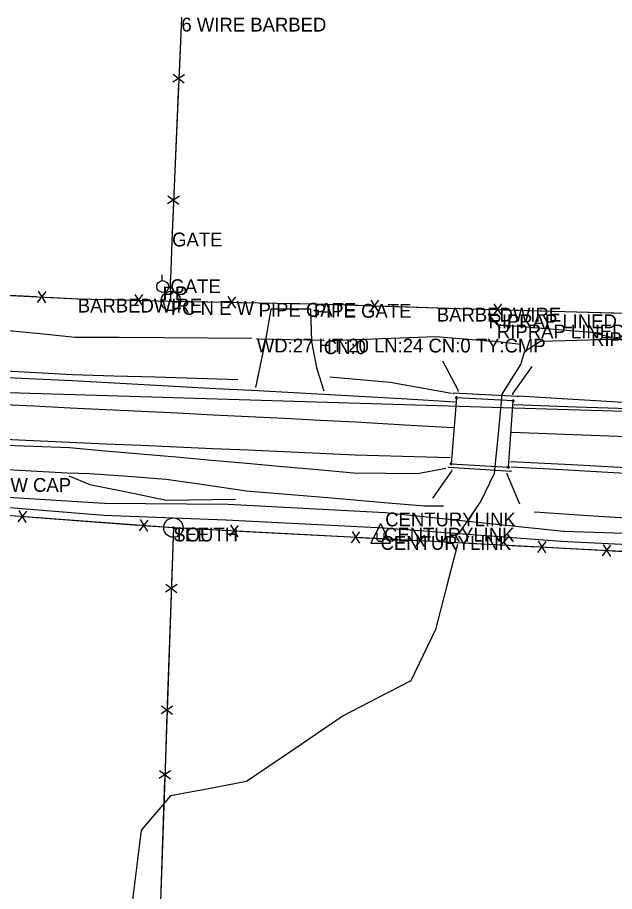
# Model space of a CAD drawing. Extents: x 675481 to 678499, y 212715 to 215285.
# Drawn here: x 676497.8 to 676713.6, y 214534.9 to 214851 of the extents above; entities that cross this region are included whole.
import ezdxf

# ---------------------------------------------------------------- set-up
doc = ezdxf.new("R2010")
doc.units = 0
for name, color, linetype in [('S_BASELINE', 7, 'Continuous'), ('S_BRIDGE', 7, 'Continuous'), ('S_DITCHLINE', 7, 'Continuous'), ('S_DRG_PT_SYM', 7, 'Continuous'), ('S_DRIVEWAY', 7, 'Continuous'), ('S_EDGE_PAVEMENT', 7, 'Continuous'), ('S_FENCE', 7, 'Continuous'), ('S_FENCE_ANNOT', 7, 'Continuous'), ('S_FIBER_OPTIC_CABLE', 7, 'Continuous'), ('S_FIBER_OPTIC_CABLE_ANNOT', 7, 'Continuous'), ('S_GATE', 7, 'Continuous'), ('S_GATE_ANNOT', 7, 'Continuous'), ('S_GRD_PT_SYM', 7, 'Continuous'), ('S_GUARDRAIL', 7, 'Continuous'), ('S_HEADWALL', 7, 'Continuous'), ('S_MISC_TOPO_POINT', 7, 'Continuous'), ('S_MSC_PT_SYM', 7, 'Continuous'), ('S_PAVEMENT_CROWN', 7, 'Continuous'), ('S_RDW_PT_SYM', 7, 'Continuous'), ('S_SECONDARY_CTL_ANNOT', 7, 'Continuous'), ('S_SHOULDER', 7, 'Continuous'), ('S_SIDE_DRAIN', 7, 'Continuous'), ('S_SIDE_DRAIN_ANNOT', 7, 'Continuous'), ('S_STR_PT_SYM', 7, 'Continuous'), ('S_STREAM', 7, 'Continuous'), ('S_UNDERGROUND_CABLE', 7, 'Continuous'), ('S_UTILITY_POLE', 7, 'Continuous'), ('S_UTILITY_POLE_ANNOT', 7, 'Continuous'), ('S_UTL_PT_SYM', 7, 'Continuous')]:
    doc.layers.add(name, color=color, linetype=linetype)

msp = doc.modelspace()

# ---------------------------------------------------------------- linework, layer by layer
at = {"layer": 'S_BASELINE'}
msp.add_line((675887.93, 214733.6), (676879.32, 214703.75), dxfattribs=at)
at = {"layer": 'S_BRIDGE'}
for p, q in [((676656.48, 214713.49), (676654.63, 214689.6)), ((676677.02, 214712.33), (676656.48, 214713.49)), ((676675.25, 214688.38), (676677.02, 214712.33)), ((676654.63, 214689.6), (676675.25, 214688.38))]:
    msp.add_line(p, q, dxfattribs=at)
at = {"layer": 'S_DITCHLINE'}
for points in [[(676266.87, 214746.32), (676281.29, 214745.11), (676295.71, 214743.91), (676310.12, 214742.71), (676324.54, 214741.51), (676347.79, 214742.46), (676371.04, 214743.4), (676394.28, 214744.35), (676417.53, 214745.3), (676430.16, 214744.06), (676442.79, 214742.83), (676455.43, 214741.59), (676468.06, 214740.36), (676480.69, 214739.12), (676493.32, 214737.89), (676505.96, 214736.65), (676518.59, 214735.42), (676534.58, 214735.32), (676550.57, 214735.23), (676566.56, 214735.13), (676582.55, 214735.04)], [(676610.25, 214734.14), (676629.62, 214734.9), (676648.99, 214735.66), (676669.38, 214733.88)], [(676679.75, 214732.77), (676669.38, 214733.88)], [(676489.68, 214687.77), (676502.73, 214687.03), (676515.78, 214686.29), (676523.98, 214686.11), (676537.73, 214685.05), (676551.48, 214684), (676565.95, 214681.92), (676580.43, 214679.85), (676596.57, 214678.47), (676612.71, 214677.1), (676628.85, 214675.72), (676644.99, 214674.34), (676651.58, 214674.33), (676651.81, 214674.32)], [(676516.3, 214685.27), (676523.99, 214682.07), (676537.85, 214679.27), (676551.71, 214676.47), (676576.57, 214676.81)], [(676684.59, 214672.17), (676686.62, 214672.03), (676704.15, 214670.89), (676721.67, 214669.74), (676734.37, 214669.15), (676747.08, 214668.56), (676759.79, 214667.97), (676772.49, 214667.38), (676785.2, 214666.79), (676797.91, 214666.21), (676810.61, 214665.62), (676823.32, 214665.03), (676844.67, 214663.84), (676866.02, 214662.65), (676887.37, 214661.46), (676908.72, 214660.27), (676914.74, 214658.57), (676915.33, 214654.64), (676902.17, 214653.74)]]:
    msp.add_lwpolyline(points, dxfattribs=at)
at = {"layer": 'S_DRG_PT_SYM'}
for points in [[(676584.32, 214734.83), (676584.32, 214734.88), (676584.32, 214734.83), (676584.27, 214734.83), (676584.32, 214734.83), (676584.32, 214734.78), (676584.32, 214734.83), (676584.37, 214734.83)], [(676608.52, 214734.24), (676608.52, 214734.29), (676608.52, 214734.24), (676608.47, 214734.24), (676608.52, 214734.24), (676608.52, 214734.19), (676608.52, 214734.24), (676608.57, 214734.24)]]:
    msp.add_lwpolyline(points, dxfattribs=at)
at = {"layer": 'S_DRIVEWAY'}
msp.add_lwpolyline([(676608.62, 214715.8), (676606.13, 214723.86), (676604.23, 214733.83), (676603.83, 214745.52), (676589.43, 214745.51), (676587.52, 214735.03), (676583.86, 214717.17)], dxfattribs=at)
at = {"layer": 'S_EDGE_PAVEMENT'}
for points in [[(676491.25, 214720.92), (676504.43, 214720.3), (676517.61, 214719.68), (676530.59, 214718.97), (676543.56, 214718.27), (676556.54, 214717.57), (676569.51, 214716.87), (676582.49, 214716.16), (676595.47, 214715.46), (676608.44, 214714.76), (676621.42, 214714.05), (676638.71, 214713.05), (676656, 214712.04)], [(676677.25, 214711.01), (676699.88, 214710.21), (676722.5, 214709.42), (676735.45, 214708.74), (676748.41, 214708.05), (676761.36, 214707.37), (676774.32, 214706.69), (676787.27, 214706.01), (676800.23, 214705.33), (676813.18, 214704.64), (676826.14, 214703.96), (676838.77, 214703.19), (676851.4, 214702.42), (676864.03, 214701.65), (676876.65, 214700.88), (676889.28, 214700.1), (676901.91, 214699.33), (676914.54, 214698.56), (676927.17, 214697.79), (676942.37, 214697.01), (676957.56, 214696.24), (676972.76, 214695.46), (676987.95, 214694.68), (676999.79, 214693.96)], [(676490.26, 214698.57), (676503.46, 214697.99), (676516.66, 214697.4), (676529.56, 214696.84), (676542.46, 214696.27), (676555.35, 214695.7), (676568.25, 214695.13), (676581.15, 214694.57), (676594.05, 214694), (676606.95, 214693.43), (676619.85, 214692.87), (676637.02, 214692.34), (676654.2, 214691.81)], [(676676.07, 214690.47), (676698.02, 214689.27), (676719.97, 214688.08), (676733, 214687.38), (676746.03, 214686.69), (676759.06, 214685.99), (676772.1, 214685.3), (676785.13, 214684.61), (676798.16, 214683.91), (676811.19, 214683.22), (676824.22, 214682.52), (676837.04, 214681.68), (676849.87, 214680.84), (676862.69, 214680), (676875.51, 214679.16), (676888.34, 214678.31), (676901.16, 214677.47), (676913.98, 214676.63), (676926.8, 214675.79), (676941.84, 214675.17), (676956.87, 214674.55), (676971.9, 214673.93), (676986.94, 214673.32), (676998.53, 214672.68)]]:
    msp.add_lwpolyline(points, dxfattribs=at)
at = {"layer": 'S_FENCE'}
for p, q in [((676557.05, 214850.91), (676553.68, 214773.19)), ((676558.2, 214830.28), (676553.99, 214827.59)), ((676554.11, 214830.46), (676558.08, 214827.41)), ((676556.3, 214786.32), (676552.08, 214783.63)), ((676552.2, 214786.5), (676556.17, 214783.46)), ((676417.3, 214754.4), (676519.59, 214749.29)), ((676553.21, 214748.45), (676553.05, 214756.3)), ((676505.08, 214747.97), (676508.15, 214751.91)), ((676505.29, 214752.06), (676507.95, 214747.82)), ((676519.59, 214749.29), (676553.21, 214748.45)), ((676540.1, 214746.73), (676543.07, 214750.75)), ((676540.21, 214750.82), (676542.97, 214746.66)), ((676553.21, 214748.45), (676584.96, 214747.76)), ((676573.72, 214745.96), (676576.68, 214749.99)), ((676573.81, 214750.05), (676576.59, 214745.89)), ((676625.38, 214744.72), (676628.37, 214748.73)), ((676625.5, 214748.81), (676628.24, 214744.63)), ((676604.89, 214747.4), (676649.4, 214746.03)), ((676649.4, 214746.03), (676723.38, 214743.86)), ((676669.9, 214743.38), (676672.89, 214747.39)), ((676670.02, 214747.47), (676672.77, 214743.29)), ((676410.39, 214677.16), (676554.15, 214666.49)), ((676497.99, 214668.6), (676501.16, 214672.48)), ((676498.3, 214672.69), (676500.85, 214668.39)), ((676541.87, 214665.35), (676545.03, 214669.22)), ((676542.17, 214669.43), (676544.73, 214665.14)), ((676554.13, 214666.5), (676542.97, 214341.43)), ((676554.15, 214666.49), (676721.59, 214657.65)), ((676574.58, 214663.36), (676577.66, 214667.3)), ((676574.8, 214667.45), (676577.44, 214663.21)), ((676618.52, 214661.04), (676621.6, 214664.98)), ((676618.73, 214665.13), (676621.38, 214660.89)), ((676641.92, 214659.81), (676645, 214663.75)), ((676642.13, 214663.9), (676644.78, 214659.66)), ((676685.86, 214657.49), (676688.94, 214661.43)), ((676686.07, 214661.58), (676688.72, 214657.34)), ((676709.26, 214656.25), (676712.34, 214660.19)), ((676709.47, 214660.34), (676712.12, 214656.1)), ((676555.47, 214645.87), (676551.28, 214643.15)), ((676551.38, 214646.01), (676555.38, 214643.01)), ((676553.96, 214601.9), (676549.77, 214599.17)), ((676549.87, 214602.04), (676553.86, 214599.03)), ((676553.16, 214578.48), (676548.97, 214575.75)), ((676549.07, 214578.62), (676553.06, 214575.61))]:
    msp.add_line(p, q, dxfattribs=at)
for points in [[(676557.05, 214850.91), (676556.18, 214830.93)], [(676556.01, 214826.94), (676554.27, 214786.98)], [(676554.13, 214783.54), (676553.68, 214773.19)], [(676553.21, 214748.45), (676553.05, 214756.3)], [(676484.64, 214751.04), (676504.62, 214750.04)], [(676508.61, 214749.84), (676519.59, 214749.29)], [(676519.59, 214749.29), (676539.59, 214748.79)], [(676543.59, 214748.69), (676553.21, 214748.45)], [(676553.21, 214748.45), (676573.2, 214748.01)], [(676577.2, 214747.93), (676584.96, 214747.76)], [(676604.89, 214747.4), (676624.88, 214746.78)], [(676628.87, 214746.66), (676649.4, 214746.03)], [(676649.4, 214746.03), (676669.39, 214745.44)], [(676673.39, 214745.32), (676713.38, 214744.15)], [(676501.57, 214670.39), (676541.46, 214667.43)], [(676544.88, 214667.18), (676554.15, 214666.49)], [(676554.13, 214666.5), (676553.45, 214646.51)], [(676554.15, 214666.49), (676574.12, 214665.44)], [(676578.12, 214665.23), (676618.06, 214663.12)], [(676621.49, 214662.94), (676641.46, 214661.88)], [(676645.45, 214661.67), (676685.4, 214659.56)], [(676688.83, 214659.38), (676708.8, 214658.33)], [(676712.79, 214658.12), (676721.59, 214657.65)], [(676553.31, 214642.51), (676551.94, 214602.54)], [(676551.82, 214599.1), (676551.13, 214579.12)], [(676550.99, 214575.12), (676549.62, 214535.14)]]:
    msp.add_lwpolyline(points, dxfattribs=at)
for centre, radius in [((676553.21, 214748.45), 3.49), ((676553.21, 214748.45), 0.247), ((676553.21, 214748.45), 0.0349), ((676554.15, 214666.5), 3.49), ((676554.15, 214666.5), 0.247), ((676554.15, 214666.5), 0.0349)]:
    msp.add_circle(centre, radius, dxfattribs=at)
at = {"layer": 'S_FIBER_OPTIC_CABLE'}
for p, q in [((676408.53, 214682.85), (676529.18, 214675.38)), ((676408.56, 214680.71), (676529.06, 214670.98)), ((676529.18, 214675.38), (676573.85, 214674.97)), ((676573.85, 214674.97), (676630.73, 214671.96)), ((676529.06, 214670.98), (676573.15, 214669.31)), ((676573.15, 214669.31), (676630.28, 214666.43)), ((676630.73, 214671.96), (676695.14, 214665.17)), ((676630.28, 214666.43), (676694.38, 214661.65)), ((676695.14, 214665.17), (676903.62, 214659.05)), ((676694.38, 214661.65), (676902.67, 214650.86))]:
    msp.add_line(p, q, dxfattribs=at)
at = {"layer": 'S_GATE'}
for p, q in [((676553.68, 214773.19), (676553.05, 214756.3)), ((676584.96, 214747.76), (676604.89, 214747.4))]:
    msp.add_line(p, q, dxfattribs=at)
at = {"layer": 'S_GRD_PT_SYM'}
for points in [[(676668.05, 214743.62), (676668.05, 214743.67), (676668.05, 214743.62), (676668, 214743.62), (676668.05, 214743.62), (676668.05, 214743.57), (676668.05, 214743.62), (676668.1, 214743.62)], [(676671.11, 214739.94), (676671.11, 214739.99), (676671.11, 214739.94), (676671.06, 214739.94), (676671.11, 214739.94), (676671.11, 214739.89), (676671.11, 214739.94), (676671.16, 214739.94)], [(676705.16, 214737.13), (676705.16, 214737.18), (676705.16, 214737.13), (676705.1, 214737.13), (676705.16, 214737.13), (676705.16, 214737.08), (676705.16, 214737.13), (676705.21, 214737.13)]]:
    msp.add_lwpolyline(points, dxfattribs=at)
at = {"layer": 'S_GUARDRAIL'}
for p, q in [((676678.64, 214713.88), (676655.35, 214715.08)), ((676653.6, 214688.39), (676676.22, 214686.95))]:
    msp.add_line(p, q, dxfattribs=at)
at = {"layer": 'S_HEADWALL'}
for points in [[(676651.4, 214726.81), (676656.98, 214716.27), (676656.94, 214715.71)], [(676676.87, 214714.58), (676676.96, 214715.07), (676683.86, 214724.82)], [(676654.8, 214687.36), (676654.71, 214686.87), (676647.86, 214677.13)], [(676679.34, 214674.94), (676674.77, 214685.8), (676674.83, 214686.23)]]:
    msp.add_lwpolyline(points, dxfattribs=at)
at = {"layer": 'S_MISC_TOPO_POINT'}
for p, q in [((676668.05, 214743.62), (676671.11, 214739.94)), ((676671.11, 214739.94), (676705.16, 214737.13)), ((676705.16, 214737.13), (676721.61, 214733.06))]:
    msp.add_line(p, q, dxfattribs=at)
at = {"layer": 'S_MSC_PT_SYM'}
for points in [[(676557.05, 214850.91), (676557.05, 214850.96), (676557.05, 214850.91), (676557, 214850.91), (676557.05, 214850.91), (676557.05, 214850.86), (676557.05, 214850.91), (676557.1, 214850.91)], [(676553.68, 214773.19), (676553.68, 214773.24), (676553.68, 214773.19), (676553.63, 214773.19), (676553.68, 214773.19), (676553.68, 214773.14), (676553.68, 214773.19), (676553.73, 214773.19)], [(676553.68, 214773.19), (676553.68, 214773.24), (676553.68, 214773.19), (676553.63, 214773.19), (676553.68, 214773.19), (676553.68, 214773.14), (676553.68, 214773.19), (676553.73, 214773.19)], [(676553.05, 214756.3), (676553.05, 214756.35), (676553.05, 214756.3), (676553, 214756.3), (676553.05, 214756.3), (676553.05, 214756.25), (676553.05, 214756.3), (676553.1, 214756.3)], [(676553.05, 214756.3), (676553.05, 214756.35), (676553.05, 214756.3), (676553, 214756.3), (676553.05, 214756.3), (676553.05, 214756.25), (676553.05, 214756.3), (676553.1, 214756.3)], [(676519.59, 214749.29), (676519.59, 214749.34), (676519.59, 214749.29), (676519.54, 214749.29), (676519.59, 214749.29), (676519.59, 214749.24), (676519.59, 214749.29), (676519.65, 214749.29)], [(676553.21, 214748.45), (676553.21, 214748.5), (676553.21, 214748.45), (676553.16, 214748.45), (676553.21, 214748.45), (676553.21, 214748.4), (676553.21, 214748.45), (676553.26, 214748.45)], [(676553.21, 214748.45), (676553.21, 214748.5), (676553.21, 214748.45), (676553.16, 214748.45), (676553.21, 214748.45), (676553.21, 214748.4), (676553.21, 214748.45), (676553.26, 214748.45)], [(676584.96, 214747.76), (676584.96, 214747.81), (676584.96, 214747.76), (676584.91, 214747.76), (676584.96, 214747.76), (676584.96, 214747.71), (676584.96, 214747.76), (676585.01, 214747.76)], [(676584.96, 214747.76), (676584.96, 214747.81), (676584.96, 214747.76), (676584.91, 214747.76), (676584.96, 214747.76), (676584.96, 214747.71), (676584.96, 214747.76), (676585.01, 214747.76)], [(676604.89, 214747.4), (676604.89, 214747.45), (676604.89, 214747.4), (676604.83, 214747.4), (676604.89, 214747.4), (676604.89, 214747.35), (676604.89, 214747.4), (676604.94, 214747.4)], [(676604.89, 214747.4), (676604.89, 214747.45), (676604.89, 214747.4), (676604.83, 214747.4), (676604.89, 214747.4), (676604.89, 214747.35), (676604.89, 214747.4), (676604.94, 214747.4)], [(676649.4, 214746.03), (676649.4, 214746.08), (676649.4, 214746.03), (676649.35, 214746.03), (676649.4, 214746.03), (676649.4, 214745.98), (676649.4, 214746.03), (676649.45, 214746.03)], [(676554.13, 214666.5), (676554.13, 214666.55), (676554.13, 214666.5), (676554.08, 214666.5), (676554.13, 214666.5), (676554.13, 214666.45), (676554.13, 214666.5), (676554.18, 214666.5)], [(676554.15, 214666.49), (676554.15, 214666.54), (676554.15, 214666.49), (676554.1, 214666.49), (676554.15, 214666.49), (676554.15, 214666.44), (676554.15, 214666.49), (676554.2, 214666.49)]]:
    msp.add_lwpolyline(points, dxfattribs=at)
at = {"layer": 'S_PAVEMENT_CROWN'}
for points in [[(676490.44, 214711.13), (676503.65, 214710.5), (676516.86, 214709.86), (676529.78, 214709.23), (676542.69, 214708.59), (676555.6, 214707.95), (676568.51, 214707.31), (676581.42, 214706.68), (676594.34, 214706.04), (676607.25, 214705.4), (676620.16, 214704.77), (676637.71, 214703.73), (676655.26, 214702.69)], [(676676.38, 214701.07), (676698.84, 214700.19), (676721.29, 214699.32), (676734.24, 214698.53), (676747.19, 214697.75), (676760.13, 214696.97), (676773.08, 214696.19), (676786.03, 214695.41), (676798.98, 214694.63), (676811.92, 214693.85), (676824.87, 214693.07), (676837.62, 214692.22), (676850.38, 214691.37), (676863.13, 214690.52), (676875.89, 214689.66), (676888.65, 214688.81), (676901.4, 214687.96), (676914.16, 214687.11), (676926.91, 214686.26), (676939.91, 214685.55), (676952.91, 214684.85), (676965.91, 214684.15), (676978.91, 214683.45), (676999.41, 214683.17)]]:
    msp.add_lwpolyline(points, dxfattribs=at)
at = {"layer": 'S_RDW_PT_SYM'}
for points in [[(676655.35, 214715.08), (676655.35, 214715.13), (676655.35, 214715.08), (676655.3, 214715.08), (676655.35, 214715.08), (676655.35, 214715.03), (676655.35, 214715.08), (676655.4, 214715.08)], [(676678.64, 214713.88), (676678.64, 214713.93), (676678.64, 214713.88), (676678.59, 214713.88), (676678.64, 214713.88), (676678.64, 214713.83), (676678.64, 214713.88), (676678.69, 214713.88)], [(676653.6, 214688.39), (676653.6, 214688.44), (676653.6, 214688.39), (676653.55, 214688.39), (676653.6, 214688.39), (676653.6, 214688.34), (676653.6, 214688.39), (676653.65, 214688.39)], [(676676.22, 214686.95), (676676.22, 214687), (676676.22, 214686.95), (676676.17, 214686.95), (676676.22, 214686.95), (676676.22, 214686.9), (676676.22, 214686.95), (676676.27, 214686.95)]]:
    msp.add_lwpolyline(points, dxfattribs=at)
at = {"layer": 'S_SHOULDER'}
for points in [[(676271.8, 214734.15), (676284.58, 214733.56), (676297.36, 214732.96), (676310.14, 214732.36), (676322.91, 214731.76), (676335.69, 214731.16), (676348.47, 214730.56), (676361.25, 214729.96), (676374.03, 214729.36), (676386.81, 214728.76), (676399.58, 214728.16), (676412.36, 214727.56), (676425.52, 214726.85), (676438.69, 214726.14), (676451.85, 214725.43), (676465.01, 214724.72), (676478.17, 214724.01), (676491.34, 214723.3), (676504.5, 214722.59), (676517.66, 214721.88), (676532.62, 214721.43), (676547.57, 214720.99), (676562.52, 214720.54), (676577.48, 214720.09)], [(676610.75, 214720.98), (676632.53, 214719.09), (676654.68, 214715.15)], [(676678.76, 214714.1), (676700.72, 214712.83), (676722.69, 214711.55), (676735.58, 214710.91), (676748.48, 214710.26), (676761.37, 214709.61), (676774.27, 214708.96), (676787.16, 214708.31), (676800.06, 214707.66), (676812.95, 214707.01), (676825.85, 214706.36), (676838.52, 214705.61), (676851.19, 214704.86), (676863.86, 214704.11), (676876.53, 214703.36), (676889.2, 214702.61), (676901.88, 214701.86), (676914.55, 214701.12), (676927.22, 214700.37), (676946.23, 214699.69), (676965.23, 214699.02), (676981.46, 214697.75), (676997.69, 214696.47)], [(676490.2, 214696.48), (676503.41, 214695.97), (676516.61, 214695.46), (676529.44, 214694.32), (676542.27, 214693.18), (676555.1, 214692.05), (676567.92, 214690.91), (676580.75, 214689.77), (676593.58, 214688.64), (676606.4, 214687.5), (676619.23, 214686.36), (676642.4, 214686.13), (676652.68, 214687.95)], [(676676.21, 214688.53), (676694.75, 214687.49), (676713.28, 214686.45), (676731.82, 214685.42), (676750.35, 214684.38), (676768.89, 214683.35), (676787.42, 214682.31), (676805.96, 214681.28), (676824.49, 214680.24), (676846.91, 214678.62), (676869.33, 214676.99), (676891.75, 214675.37), (676914.16, 214673.75)]]:
    msp.add_lwpolyline(points, dxfattribs=at)
at = {"layer": 'S_SIDE_DRAIN'}
msp.add_line((676584.32, 214734.83), (676608.52, 214734.24), dxfattribs=at)
at = {"layer": 'S_STR_PT_SYM'}
for points in [[(676656.48, 214713.49), (676656.48, 214713.99), (676656.48, 214713.49), (676655.98, 214713.49), (676656.48, 214713.49), (676656.48, 214712.99), (676656.48, 214713.49), (676656.98, 214713.49)], [(676677.02, 214712.33), (676677.02, 214712.83), (676677.02, 214712.33), (676676.52, 214712.33), (676677.02, 214712.33), (676677.02, 214711.83), (676677.02, 214712.33), (676677.52, 214712.33)], [(676654.63, 214689.6), (676654.63, 214690.1), (676654.63, 214689.6), (676654.13, 214689.6), (676654.63, 214689.6), (676654.63, 214689.1), (676654.63, 214689.6), (676655.13, 214689.6)], [(676675.25, 214688.38), (676675.25, 214688.88), (676675.25, 214688.38), (676674.75, 214688.38), (676675.25, 214688.38), (676675.25, 214687.88), (676675.25, 214688.38), (676675.75, 214688.38)]]:
    msp.add_lwpolyline(points, dxfattribs=at)
at = {"layer": 'S_STREAM'}
for points in [[(676657.59, 214664.66), (676665.25, 214675.97), (676670.25, 214686.15), (676671.66, 214700.47), (676673.06, 214714.79), (676679.72, 214725.51), (676681.18, 214730.35), (676686.85, 214733.98), (676704.61, 214734.46), (676722.37, 214734.95)], [(676656.9, 214660.42), (676652.9, 214645.03), (676648.89, 214629.64), (676640.01, 214611.09), (676627.78, 214604.76), (676615.55, 214598.43), (676598.06, 214586.54), (676580.57, 214574.66), (676566.84, 214572.06), (676553.12, 214569.47), (676542.48, 214557.03), (676540.9, 214544.47), (676539.31, 214531.91), (676537.72, 214519.35), (676536.14, 214506.79)]]:
    msp.add_lwpolyline(points, dxfattribs=at)
at = {"layer": 'S_UNDERGROUND_CABLE'}
for p, q in [((676629.06, 214667.98), (676625.53, 214660.89)), ((676629.06, 214667.98), (676632.54, 214660.89)), ((676627.85, 214662.13), (676627.85, 214664.57)), ((676630.22, 214664.57), (676630.22, 214662.13)), ((676625.53, 214660.89), (676632.54, 214660.89)), ((676628.47, 214661.47), (676627.85, 214662.13)), ((676629.68, 214661.47), (676628.47, 214661.47)), ((676630.22, 214662.13), (676629.68, 214661.47))]:
    msp.add_line(p, q, dxfattribs=at)
at = {"layer": 'S_UTILITY_POLE'}
msp.add_line((676550.14, 214755.83), (676550.14, 214757.93), dxfattribs=at)
msp.add_circle((676550.26, 214753.68), 2.13, dxfattribs=at)
at = {"layer": 'S_UTL_PT_SYM'}
for points in [[(676529.18, 214675.38), (676529.18, 214675.43), (676529.18, 214675.38), (676529.12, 214675.38), (676529.18, 214675.38), (676529.18, 214675.33), (676529.18, 214675.38), (676529.23, 214675.38)], [(676573.85, 214674.97), (676573.85, 214675.02), (676573.85, 214674.97), (676573.8, 214674.97), (676573.85, 214674.97), (676573.85, 214674.92), (676573.85, 214674.97), (676573.9, 214674.97)], [(676529.06, 214670.98), (676529.06, 214671.03), (676529.06, 214670.98), (676529.01, 214670.98), (676529.06, 214670.98), (676529.06, 214670.93), (676529.06, 214670.98), (676529.11, 214670.98)], [(676573.15, 214669.31), (676573.15, 214669.36), (676573.15, 214669.31), (676573.1, 214669.31), (676573.15, 214669.31), (676573.15, 214669.26), (676573.15, 214669.31), (676573.2, 214669.31)], [(676630.73, 214671.96), (676630.73, 214672), (676630.73, 214671.96), (676630.68, 214671.96), (676630.73, 214671.96), (676630.73, 214671.9), (676630.73, 214671.96), (676630.78, 214671.96)], [(676630.28, 214666.43), (676630.28, 214666.48), (676630.28, 214666.43), (676630.23, 214666.43), (676630.28, 214666.43), (676630.28, 214666.38), (676630.28, 214666.43), (676630.33, 214666.43)], [(676695.14, 214665.17), (676695.14, 214665.22), (676695.14, 214665.17), (676695.09, 214665.17), (676695.14, 214665.17), (676695.14, 214665.12), (676695.14, 214665.17), (676695.19, 214665.17)], [(676694.38, 214661.65), (676694.38, 214661.71), (676694.38, 214661.65), (676694.33, 214661.65), (676694.38, 214661.65), (676694.38, 214661.61), (676694.38, 214661.65), (676694.43, 214661.65)]]:
    msp.add_lwpolyline(points, dxfattribs=at)

# ---------------------------------------------------------------- texts
at = {"layer": 'S_FENCE_ANNOT'}
for s, p in [('6 WIRE BARBED', (676557.05, 214845.91)), ('GATE', (676553.68, 214768.19)), ('GATE', (676553.05, 214751.3)), ('BARBEDWIRE', (676519.59, 214744.29)), ('FC N E W', (676553.21, 214743.45)), ('FC N E W', (676553.21, 214743.45)), ('FC N E W', (676553.21, 214743.45)), ('PIPE GATE', (676584.96, 214742.76)), ('PIPE GATE', (676604.89, 214742.4)), ('BARBEDWIRE', (676649.4, 214741.03)), ('TEE', (676554.15, 214661.5)), ('SOUTH', (676554.13, 214661.5))]:
    msp.add_text(s, height=5, dxfattribs=at).set_placement(p)
at = {"layer": 'S_FIBER_OPTIC_CABLE_ANNOT'}
for p in [(676630.73, 214666.96), (676630.28, 214661.43)]:
    msp.add_text('CENTURYLINK', height=5, dxfattribs=at).set_placement(p)
at = {"layer": 'S_GATE_ANNOT'}
for s, p in [('GATE', (676553.68, 214768.19)), ('GATE', (676553.05, 214751.3)), ('PIPE GATE', (676584.96, 214742.76)), ('PIPE GATE', (676604.89, 214742.4))]:
    msp.add_text(s, height=5, dxfattribs=at).set_placement(p)
at = {"layer": 'S_MISC_TOPO_POINT'}
for p in [(676668.05, 214738.62), (676671.11, 214734.94), (676705.16, 214732.13)]:
    msp.add_text('RIPRAP LINED DITCH', height=5, dxfattribs=at).set_placement(p)
at = {"layer": 'S_SECONDARY_CTL_ANNOT'}
msp.add_text('PD:REBAR WCAP REBAR W CAP', height=5, dxfattribs=at).set_placement((676412.39, 214679.43))
at = {"layer": 'S_SIDE_DRAIN_ANNOT'}
for s, p in [('WD:27 HT:20 LN:24 CN:0 TY:CMP', (676584.32, 214729.83)), ('CN:0', (676608.52, 214729.24))]:
    msp.add_text(s, height=5, dxfattribs=at).set_placement(p)
at = {"layer": 'S_UTILITY_POLE_ANNOT'}
for s, p in [('PP', (676550.26, 214748.68)), ('CENTURYLINK', (676629.06, 214658.45))]:
    msp.add_text(s, height=5, dxfattribs=at).set_placement(p)

doc.saveas('drawing.dxf')
